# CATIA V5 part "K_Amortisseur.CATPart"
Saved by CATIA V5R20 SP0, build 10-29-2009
Part number: Amortisseur
Bounding box of the stored display mesh (mm): x -106.994 to -67.006, y -76.066 to 157.171, z -117.171 to 116.066
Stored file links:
  G:\Khaled_CFAO_2011\ST2M\ST2M_GR2\plakomicki\Khaled\CAD_ThinkMOTION\K_Amortisseur.CATPart
  G:\Khaled_CFAO_2011\ST2M\ST2M_GR2\plakomicki\Khaled\CAD_ThinkMOTION\K_Jambe.CATProduct
  G:\Khaled_CFAO_2011\ST2M\ST2M_GR2\plakomicki\Khaled\CAD_ThinkMOTION\K_Bielle_liaison.CATPart
  G:\Khaled_CFAO_2011\ST2M\ST2M_GR2\plakomicki\Khaled\CAD_ThinkMOTION\K_Squel_Amortisseur.CATPart
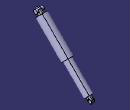
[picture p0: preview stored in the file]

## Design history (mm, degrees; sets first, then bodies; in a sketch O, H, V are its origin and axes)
External parameters (linked from other documents)
  External.Longueur_structure = 300 mm
Set1
  Plane1: linked copy from another document
  Point1: linked copy from another document
  Point2: linked copy from another document
  Plane2: linked copy from another document
  DatumCurve1: linked copy from another document
  Line1 "longueur_amortisseur": linked copy from another document
Body1 (main body)
  Sketch1 on Plane1, origin (-87, 0, 0), H (0, 1, 0), V (0, 0, 1)
    construction line L1 (148.1873, -108.1873) -> (-66.066, 106.066)
    point P1 (148.1873, -108.1873)
    point P2 (-66.066, 106.066)
    reference projected point E1 (148.1873, -108.1873) from Point1
    reference projected point E2 (-66.066, 106.066) from Point2
    line L2 (-55.4594, 95.4594) -> (-41.3173, 109.6016)
    point P3 (-55.4594, 95.4594)
    line L3 (-41.3173, 109.6016) -> (64.7487, 3.5355)
    line L4 (64.7487, 3.5355) -> (61.2132, 0)
    point P6 (61.2132, 0)
    line L5 (61.2132, 0) -> (148.1873, -86.9741)
    point P7 (61.2132, 0)
    point P8 (148.1873, -86.9741)
    line L6 (148.1873, -86.9741) -> (137.5807, -97.5807)
    point P9 (137.5807, -97.5807)
    point P10 (148.1873, -86.9741)
    line L7 (-55.4594, 95.4594) -> (137.5807, -97.5807)
    length L6 = 15
    length L2 = 20
    distance P1 L6 = 15
    distance P2 P3 = 15
    length L3 = 150 {= External.Longueur_structure /2}
    coincidence: E1 P1, E2 P2, P3 L1, P9 L1, P8 P10, P6 P7
    perpendicularity: L2 L1, L3 L4, L5 L4, L6 L1, L3 L2
    parallelism: L3 L1, L4 L2, L6 L4, L7 L1
  Sketch2 on Plane2, origin (-87, 0, 0), H (0, 1, 0), V (0, 0, 1)
    circle A1 centre (-66.066, 106.066) radius 7.5
    point P1 (-66.066, 106.066)
    reference projected point E1 (-66.066, 106.066) from Point2
    radius A1 = 7.5
    coincidence: P1 E1
  Pad1: profile Sketch2, direction (-1, 0, 0), length 15, mirrored extent
  Shaft1: profile Sketch1, axis Sketch1.L7, angle 360
  Sketch3 on Plane2, origin (-87, 0, 0), H (0, 1, 0), V (0, 0, 1)
    circle A1 centre (-66.066, 106.066) radius 7.5
    point P1 (-66.066, 106.066)
    reference projected circle E1 centre (-66.066, 106.066) radius 7.5 from edge [face of Pad1 from Sketch2.A1 | start face of Pad1]
    reference projected circle E2 centre (-66.066, 106.066) radius 7.5 from edge [face of Pad1 from Sketch2.A1 | start face of Pad1]
    point P2 (-66.066, 106.066)
    arc A2 centre (-66.066, 106.066) radius 10 from (-58.9949, 113.1371) to (-73.1371, 98.9949) ccw
    line L1 (6.766, 16.2635) -> (23.7365, 33.234)
    point P3 (6.766, 16.2635)
    point P4 (23.7365, 33.234)
    reference intersected line E3 (8.1802, 17.6777) -> (22.3223, 31.8198) from face of Shaft1 from Sketch1.L2
    construction line L2 (15.2513, 24.7487) -> (-66.066, 106.066)
    point P5 (15.2513, 24.7487)
    point P6 (-66.066, 106.066)
    line L3 (6.766, 16.2635) -> (-0.3051, 23.3345)
    line L4 (23.7365, 33.234) -> (16.6655, 40.3051)
    point P8 (23.7365, 33.234)
    point P9 (16.6655, 40.3051)
    construction line L5 (-39.9671, 132.165) -> (-58.9949, 113.1371)
    point P10 (-58.9949, 113.1371)
    axis line L6 (-66.066, 106.066) -> (-73.1371, 98.9949)
    point P11 (-73.1371, 98.9949)
    point P12 (-58.9949, 113.1371)
    point P13 (16.6655, 40.3051)
    point P14 (-73.1371, 98.9949)
    line L7 (-58.9949, 113.1371) -> (16.6655, 40.3051)
    line L8 (-0.3051, 23.3345) -> (-73.1371, 98.9949)
    point P16 (-73.1371, 98.9949)
    radius A2 = 10
    distance P3 L2 = 12
    distance P4 L2 = 12
    length L4 = 10
    length L3 = 10
    concentricity: P1 E1
    coincidence: A1 E2, P2 P1, L1 E3, P6 P2, P5 L1, P8 L1, P8 P4, A2 P10, P12 L5, P13 L4, P14 A2, P14 L6, P13 P9, P12 P10, L5 P1, P16 A2, P16 L6, P11 P16
    perpendicularity: L1 L2, L2 L5, L6 L2
    parallelism: L3 L2, L4 L2, L5 L1, L6 L5
  Pad2: profile Sketch3, direction (1, 0, 0), length 7.5, mirrored extent
  Fillet1: radius 5, on face of Pad2 from Sketch3.A2; face of Pad2 from Sketch3.L8
  Sketch4 on Plane1, origin (-87, 0, 0), H (0, 1, 0), V (0, 0, 1)
    circle A1 centre (148.1873, -108.1873) radius 7.5
    point P1 (148.1873, -108.1873)
    reference projected circle E1 centre (148.1873, -108.1873) radius 7.5 from edge of DatumCurve1
    reference projected circle E2 centre (148.1873, -108.1873) radius 7.5 from edge of DatumCurve1
    arc A2 centre (148.1873, -108.1873) radius 9 from (141.8234, -114.5513) to (154.5513, -101.8234) ccw
    point P2 (148.1873, -108.1873)
    reference projected point E3 (148.1873, -108.1873) from Point1
    line L1 (73.9411, -19.799) -> (59.799, -33.9411)
    point P3 (73.9411, -19.799)
    point P4 (59.799, -33.9411)
    reference projected line E4 (77.4767, -16.2635) -> (56.2635, -37.4767) from edge [face of Shaft1 from Sketch1.L5 | face of Shaft1 from Sketch1.L6]
    axis line L2 (154.5513, -101.8234) -> (141.8234, -114.5513)
    point P5 (154.5513, -101.8234)
    reference projected point E5 (148.1873, -108.1873) from Point1
    reference projected line E6 (-30.7107, 70.7107) -> (112.832, -72.832) from Line1
    reference projected line E7 (-30.7107, 70.7107) -> (112.832, -72.832) from Line1
    line L3 (73.9411, -19.799) -> (81.0122, -26.8701)
    point P7 (81.0122, -26.8701)
    line L4 (59.799, -33.9411) -> (66.8701, -41.0122)
    point P8 (66.8701, -41.0122)
    line L5 (141.8234, -114.5513) -> (66.8701, -41.0122)
    point P9 (66.8701, -41.0122)
    point P10 (154.5513, -101.8234)
    line L6 (154.5513, -101.8234) -> (81.0122, -26.8701)
    point P11 (154.5513, -101.8234)
    point P12 (81.0122, -26.8701)
    radius A2 = 9
    distance P4 E6 = 10
    distance P3 E7 = 10
    length L4 = 10
    length L3 = 10
    concentricity: P1 E1
    coincidence: A1 E2, P2 E3, L1 E4, L2 E5, P9 L4, L5 P8, P10 A2, P10 L2, P11 P5, P12 P7, P8 P9
    parallelism: L1 L2, L4 L3
    perpendicularity: L3 L2, L3 L1, L4 L1
  Pad3: profile Sketch4, direction (1, 0, 0), length 7.5, mirrored extent
  Fillet2: radius 5, on face of Pad3 from Sketch4.A2; face of Pad3 from Sketch4.L5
